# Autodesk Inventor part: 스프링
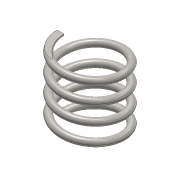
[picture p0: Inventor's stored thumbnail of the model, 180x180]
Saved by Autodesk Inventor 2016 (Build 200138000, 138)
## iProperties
Created: 2017-07
Part Number: 스프링
Material: 스테인레스 스틸
Document SubType Name: Modeling
Designer: KSEW
Mass: 5.27004 g
Surface Area: 13.4118 cm^2
Volume: 0.658755 cm^3
Density: 8 g/cm^3
Appearance: 반연마
Author: KSEW
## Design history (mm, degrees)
sketch "스케치1"
  geometry: L1 (0, 20.5)-(8.5, 20.5); L2 (8.5, 20.5)-(8.5, 0); L3 (8.5, 0)-(0, 0); L4 (0, 0)-(0, 20.5); C1 r 1 at (8.5, 0); 1 further point
  constraints: 8 end point, 2 coincident, 2 parallel, 1 centre point, 1 horizontal, 1 perpendicular
  dimensions: "d0" = 17 diameter of L2 L4; "d1" = 20.5 distance of L1.end L2.end (derived); "d2" = 2 diameter of C1
feature "코일1" pitch "d3" = 10; turns "d5" = 4; dims "d4" = 20.5 (= d1), "d6" = 0, angle "d7" = 90 deg, angle "d8" = 90 deg, "d9" = 0, "d10" = 0
sketch "스케치2"
  geometry: L1 (-7.5, 0)-(-9.5, 0) reference; 1 further point
  constraints: 1 horizontal alignment
extrude "돌출1" cut sketch "스케치2" stored distance "d11" = 10; taper "d12" = 0 deg
node "작업 평면1"
sketch "스케치3"
  geometry: L1 (7.5, 0)-(9.5, 0) reference; 1 further point
  constraints: 1 horizontal alignment
extrude "돌출2" cut sketch "스케치3" stored distance "d14" = 10; taper "d15" = 0 deg
node "솔리드1"
node "절단 모서리 투영1"
node "절단 모서리 투영2"
other parameters: "d13" = 90 deg
